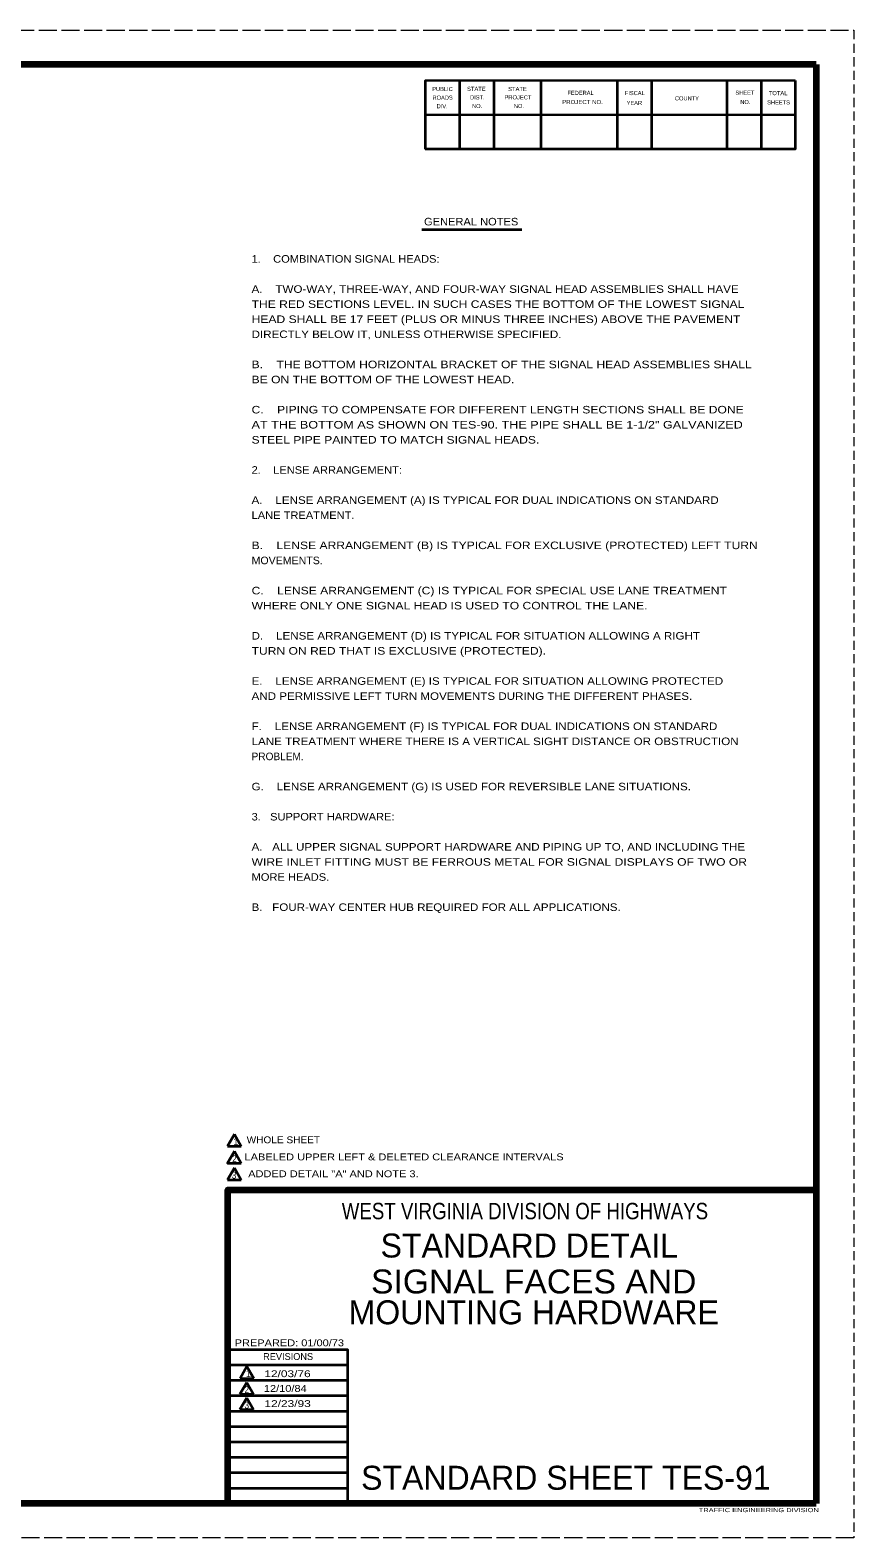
# Model space of a CAD drawing. Extents: x -295 to 385, y -102 to 338.
# Drawn here: x 144.5 to 384.8, y -101.6 to 338.4 of the extents above; entities that cross this region are included whole.
import ezdxf
from ezdxf.enums import TextEntityAlignment as Align

# ---------------------------------------------------------------- set-up
doc = ezdxf.new("R2010")
doc.units = 0
doc.header["$LTSCALE"] = 0.88
doc.linetypes.add('LONG_DASHED', pattern=[7.5, 6, -1.5])
doc.linetypes.add('MEDIUM_DASHED', pattern=[4.5, 3, -1.5])
doc.layers.add('1', color=7, linetype='Continuous', lineweight=53)
doc.layers.add('61', color=7, linetype='Continuous', lineweight=35)

msp = doc.modelspace()

# ---------------------------------------------------------------- linework, layer by layer
at = {"layer": '1', "linetype": 'MEDIUM_DASHED', "lineweight": 13}
msp.add_line((384.8107, 338.4444), (384.7907, -101.5756), dxfattribs=at)
at = {"layer": '1', "lineweight": 35}
for p, q in [((258.7414, 280.2462), (287.9667, 280.2462)), ((204.0584, 16.2171), (202.0584, 12.753)), ((204.0584, 16.2171), (206.0584, 12.753)), ((202.0584, 12.753), (206.0584, 12.753)), ((204.0584, 11.2297), (206.0584, 7.7657)), ((204.0583, 6.3917), (202.0583, 2.9276)), ((204.0583, 6.3917), (206.0583, 2.9276)), ((202.0583, 2.9276), (206.0583, 2.9276)), ((237.1907, -51.1556), (202.2107, -51.1556)), ((207.7363, -51.6016), (205.7363, -55.0657)), ((207.7363, -51.6016), (209.7363, -55.0657)), ((237.1907, -55.6556), (202.2107, -55.6556)), ((207.674, -56.2148), (205.674, -59.6789)), ((205.7363, -55.0657), (209.7363, -55.0657)), ((207.674, -56.2148), (209.674, -59.6789)), ((237.1907, -60.1556), (202.2107, -60.1556)), ((205.674, -59.6789), (209.674, -59.6789)), ((207.674, -60.7133), (205.674, -64.1774)), ((207.674, -60.7133), (209.674, -64.1774)), ((237.1907, -64.6756), (202.2107, -64.6756)), ((205.674, -64.1774), (209.674, -64.1774)), ((237.1907, -69.1556), (202.2107, -69.1556)), ((237.1907, -73.6356), (202.2107, -73.6356)), ((237.1907, -78.1356), (202.2107, -78.1356)), ((237.1907, -82.6356), (202.2107, -82.6356)), ((237.1907, -87.1556), (202.2107, -87.1556))]:
    msp.add_line(p, q, dxfattribs=at)
for points in [[(204.0584, 11.2297), (202.0584, 7.7657), (206.0584, 7.7657)], [(237.1907, -91.6356), (237.1907, -46.6756), (202.2107, -46.6756)]]:
    msp.add_lwpolyline(points, dxfattribs=at)
at = {"layer": '1', "lineweight": 158}
msp.add_lwpolyline([(202.1907, -91.5956), (202.1907, -0.0156), (373.8507, -0.0156)], dxfattribs=at)
at = {"layer": '61', "linetype": 'LONG_DASHED', "lineweight": 13}
for p, q in [((-295.2093, 338.4444), (384.8107, 338.4444)), ((384.7907, -101.5756), (-295.2693, -101.5956))]:
    msp.add_line(p, q, dxfattribs=at)
at = {"layer": '61', "lineweight": 158}
for p, q in [((373.8307, 328.4444), (373.8507, -91.5956)), ((373.8507, -91.5956), (-265.2093, -91.5756))]:
    msp.add_line(p, q, dxfattribs=at)
at = {"layer": '61'}
for p, q in [((269.7507, 323.6844), (269.7507, 303.6844)), ((279.7507, 323.6844), (279.7507, 303.6844)), ((293.4307, 323.6844), (293.4307, 303.6844)), ((315.7507, 323.6844), (315.7507, 303.6844)), ((325.7507, 323.6844), (325.7507, 303.6844)), ((347.7307, 323.7044), (347.7307, 303.7044)), ((357.7307, 323.7044), (357.7307, 303.7044)), ((367.7507, 313.6644), (259.7307, 313.6844))]:
    msp.add_line(p, q, dxfattribs=at)
at = {"layer": '61', "lineweight": 158}
msp.add_lwpolyline([(373.8307, 328.4444), (-265.2093, 328.4444), (-265.2093, -91.5756)], dxfattribs=at)
at = {"layer": '61'}
for points in [[(367.7307, 323.7044), (259.7507, 323.6844), (259.7507, 303.6844)], [(367.7307, 323.7044), (367.7307, 303.7044), (259.7507, 303.6844)]]:
    msp.add_lwpolyline(points, dxfattribs=at)

# ---------------------------------------------------------------- texts
at = {"layer": '1'}
for s, height, width, p in [('GENERAL NOTES', 2.2, 1.1, (273.1476, 281.4574)), ('WHOLE SHEET', 2, 1.1, (218.354, 13.5704)), ('2', 2, 0.9, (204.0785, 8.0443)), ('LABELED UPPER LEFT & DELETED CLEARANCE INTERVALS', 2, 1.2, (253.5784, 8.5914)), ('3', 2, 0.9, (203.9689, 3.2526)), ('ADDED DETAIL "A" AND NOTE 3.', 2, 1.2, (232.9521, 3.6548)), ('WEST VIRGINIA DIVISION OF HIGHWAYS', 4.795, 0.85, (288.839, -8.6156)), ('SIGNAL FACES AND', 6.993, 1.05, (291.4052, -30.2718)), ('2', 2, 0.9, (207.6626, -59.3633)), ('3', 2, 0.9, (207.6626, -63.8618))]:
    msp.add_text(s, height=height, dxfattribs=dict(at, width=width)).set_placement(p, align=Align.CENTER)
for s, height, width, p in [('1.    COMBINATION SIGNAL HEADS:', 2.2, 1.1, (209.0797, 270.5773)), ('A.    TWO-WAY, THREE-WAY, AND FOUR-WAY SIGNAL HEAD ASSEMBLIES SHALL HAVE', 2.2, 1.15, (209.0797, 261.7773)), ('THE RED SECTIONS LEVEL. IN SUCH CASES THE BOTTOM OF THE LOWEST SIGNAL', 2.2, 1.2, (209.0797, 257.3773)), ('HEAD SHALL BE 17 FEET (PLUS OR MINUS THREE INCHES) ABOVE THE PAVEMENT', 2.2, 1.2, (209.0797, 252.9773)), ('DIRECTLY BELOW IT, UNLESS OTHERWISE SPECIFIED.', 2.2, 1.15, (209.0797, 248.5773)), ('B.    THE BOTTOM HORIZONTAL BRACKET OF THE SIGNAL HEAD ASSEMBLIES SHALL', 2.2, 1.2, (209.0797, 239.7773)), ('BE ON THE BOTTOM OF THE LOWEST HEAD.', 2.2, 1.2, (209.0797, 235.3773)), ('AT THE BOTTOM AS SHOWN ON TES-90. THE PIPE SHALL BE 1-1/2" GALVANIZED', 2.2, 1.25, (209.0797, 222.1773)), ('C.    PIPING TO COMPENSATE FOR DIFFERENT LENGTH SECTIONS SHALL BE DONE', 2.2, 1.2, (209.0797, 226.5773)), ('STEEL PIPE PAINTED TO MATCH SIGNAL HEADS.', 2.2, 1.2, (209.0797, 217.7773)), ('2.    LENSE ARRANGEMENT:', 2.2, 1.1, (209.0797, 208.9773)), ('A.    LENSE ARRANGEMENT (A) IS TYPICAL FOR DUAL INDICATIONS ON STANDARD', 2.2, 1.15, (209.0797, 200.1773)), ('LANE TREATMENT.', 2.2, 1.1, (209.0797, 195.7773)), ('B.    LENSE ARRANGEMENT (B) IS TYPICAL FOR EXCLUSIVE (PROTECTED) LEFT TURN', 2.2, 1.2, (209.0797, 186.9773)), ('MOVEMENTS.', 2.2, 1.05, (209.0797, 182.5773)), ('C.    LENSE ARRANGEMENT (C) IS TYPICAL FOR SPECIAL USE LANE TREATMENT', 2.2, 1.2, (209.0797, 173.7773)), ('WHERE ONLY ONE SIGNAL HEAD IS USED TO CONTROL THE LANE.', 2.2, 1.2, (209.0797, 169.3773)), ('D.    LENSE ARRANGEMENT (D) IS TYPICAL FOR SITUATION ALLOWING A RIGHT', 2.2, 1.15, (209.0797, 160.5773)), ('TURN ON RED THAT IS EXCLUSIVE (PROTECTED).', 2.2, 1.2, (209.0797, 156.1773)), ('E.    LENSE ARRANGEMENT (E) IS TYPICAL FOR SITUATION ALLOWING PROTECTED', 2.2, 1.15, (209.0797, 147.3773)), ('AND PERMISSIVE LEFT TURN MOVEMENTS DURING THE DIFFERENT PHASES.', 2.2, 1.15, (209.0797, 142.9773)), ('F.    LENSE ARRANGEMENT (F) IS TYPICAL FOR DUAL INDICATIONS ON STANDARD', 2.2, 1.15, (209.0797, 134.1773)), ('LANE TREATMENT WHERE THERE IS A VERTICAL SIGHT DISTANCE OR OBSTRUCTION', 2.2, 1.15, (209.0797, 129.7773)), ('G.    LENSE ARRANGEMENT (G) IS USED FOR REVERSIBLE LANE SITUATIONS.', 2.2, 1.15, (209.0797, 116.5773)), ('3.   SUPPORT HARDWARE:', 2.2, 1.1, (209.0797, 107.7773)), ('A.   ALL UPPER SIGNAL SUPPORT HARDWARE AND PIPING UP TO, AND INCLUDING THE', 2.2, 1.15, (209.0797, 98.9773)), ('WIRE INLET FITTING MUST BE FERROUS METAL FOR SIGNAL DISPLAYS OF TWO OR', 2.2, 1.2, (209.0797, 94.5773)), ('MORE HEADS.', 2.2, 1.1, (209.0797, 90.1773)), ('B.   FOUR-WAY CENTER HUB REQUIRED FOR ALL APPLICATIONS.', 2.2, 1.15, (209.0797, 81.3773)), ('PREPARED: 01/00/73', 1.998, 1.2, (204.1507, -45.6756)), ('12/03/76', 1.998, 1.3, (212.7986, -54.6963)), ('12/10/84', 1.998, 1.2, (212.674, -58.9979)), ('12/23/93', 1.998, 1.3, (212.8317, -63.4175)), ('TRAFFIC ENGINEERING DIVISION', 1.2, 1.35, (339.5707, -94.0956))]:
    msp.add_text(s, height=height, dxfattribs=dict(at, width=width)).set_placement(p)
for s, height, p in [('PROBLEM.', 2.2, (209.0797, 125.3773)), ('REVISIONS', 1.998, (212.4707, -49.6756)), ('STANDARD SHEET TES-91', 6.993, (241.0307, -87.5556))]:
    msp.add_text(s, height=height, dxfattribs=at).set_placement(p)
for s, height, p in [('1', 2, (204.4829, 13.078)), ('STANDARD DETAIL', 6.993, (290.1076, -19.7756)), ('MOUNTING HARDWARE', 6.993, (291.4051, -39.2645)), ('1', 2, (208.1765, -54.6253))]:
    msp.add_text(s, height=height, dxfattribs=at).set_placement(p, align=Align.CENTER)
at = {"layer": '61'}
for s, rotation, p in [('PUBLIC', 0.033, (261.7907, 320.6644)), ('ROADS', 0.124, (261.8707, 318.1444)), ('DIV.', 359.932, (263.0707, 315.6444)), ('DIST.', 0.056, (272.8307, 318.2244)), ('FEDERAL', 0.007, (301.2507, 319.5444)), ('FISCAL', 359.942, (317.9907, 319.4844)), ('YEAR', 0.105, (318.5107, 316.5844)), ('COUNTY', 0.069, (332.6107, 317.9444)), ('SHEET', 0.059, (350.2507, 319.6044)), ('SHEETS', 359.959, (359.5307, 316.7644))]:
    msp.add_text(s, height=1.201, rotation=rotation, dxfattribs=at).set_placement(p)
for s, rotation, width, p in [('STATE', 0.059, 1.05, (271.9507, 320.7244)), ('STATE', 0.059, 1.05, (283.9507, 320.6644)), ('NO.', 359.852, 0.95, (273.4107, 315.7044)), ('PROJECT', 359.908, 1.05, (282.8707, 318.2444)), ('NO.', 0.225, 0.95, (285.6107, 315.7044)), ('PROJECT NO.', 359.922, 1.1, (299.7107, 316.8844)), ('NO.', 359.852, 0.95, (351.6707, 316.8844)), ('TOTAL', 359.926, 1.05, (359.9907, 319.4644))]:
    msp.add_text(s, height=1.201, rotation=rotation, dxfattribs=dict(at, width=width)).set_placement(p)

doc.saveas('drawing.dxf')
